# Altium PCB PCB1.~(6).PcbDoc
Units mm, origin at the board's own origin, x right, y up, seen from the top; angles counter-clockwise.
Board outline 48.89 x 49.4 mm, 2 copper layers (Top Layer, Bottom Layer); 29 components, 25 nets, 116 pads, 0 vias.
Unrouted connection lines stored in the file: 7.
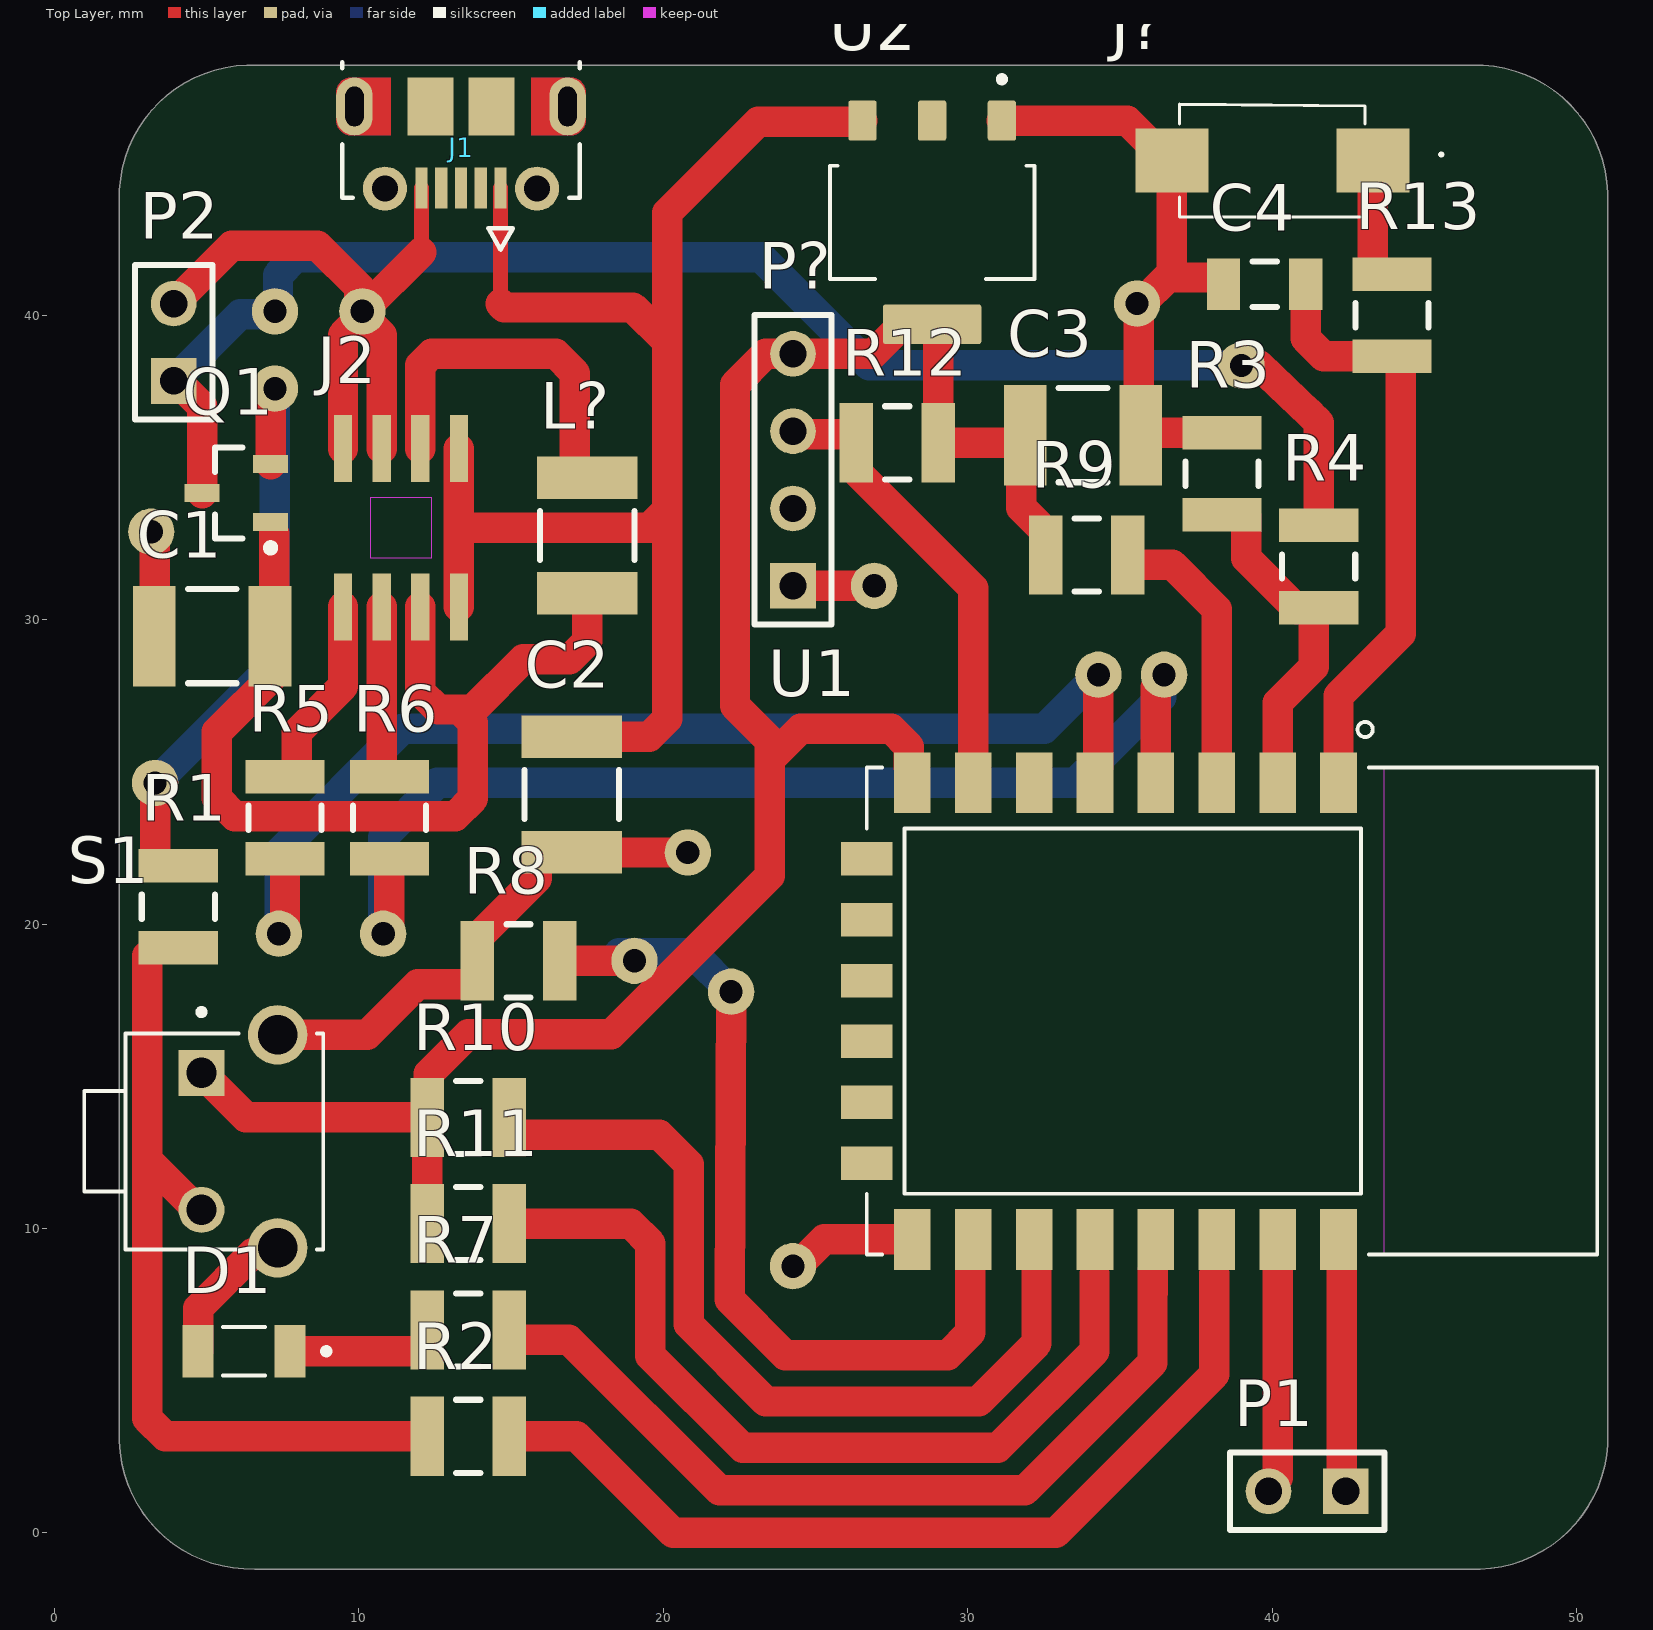
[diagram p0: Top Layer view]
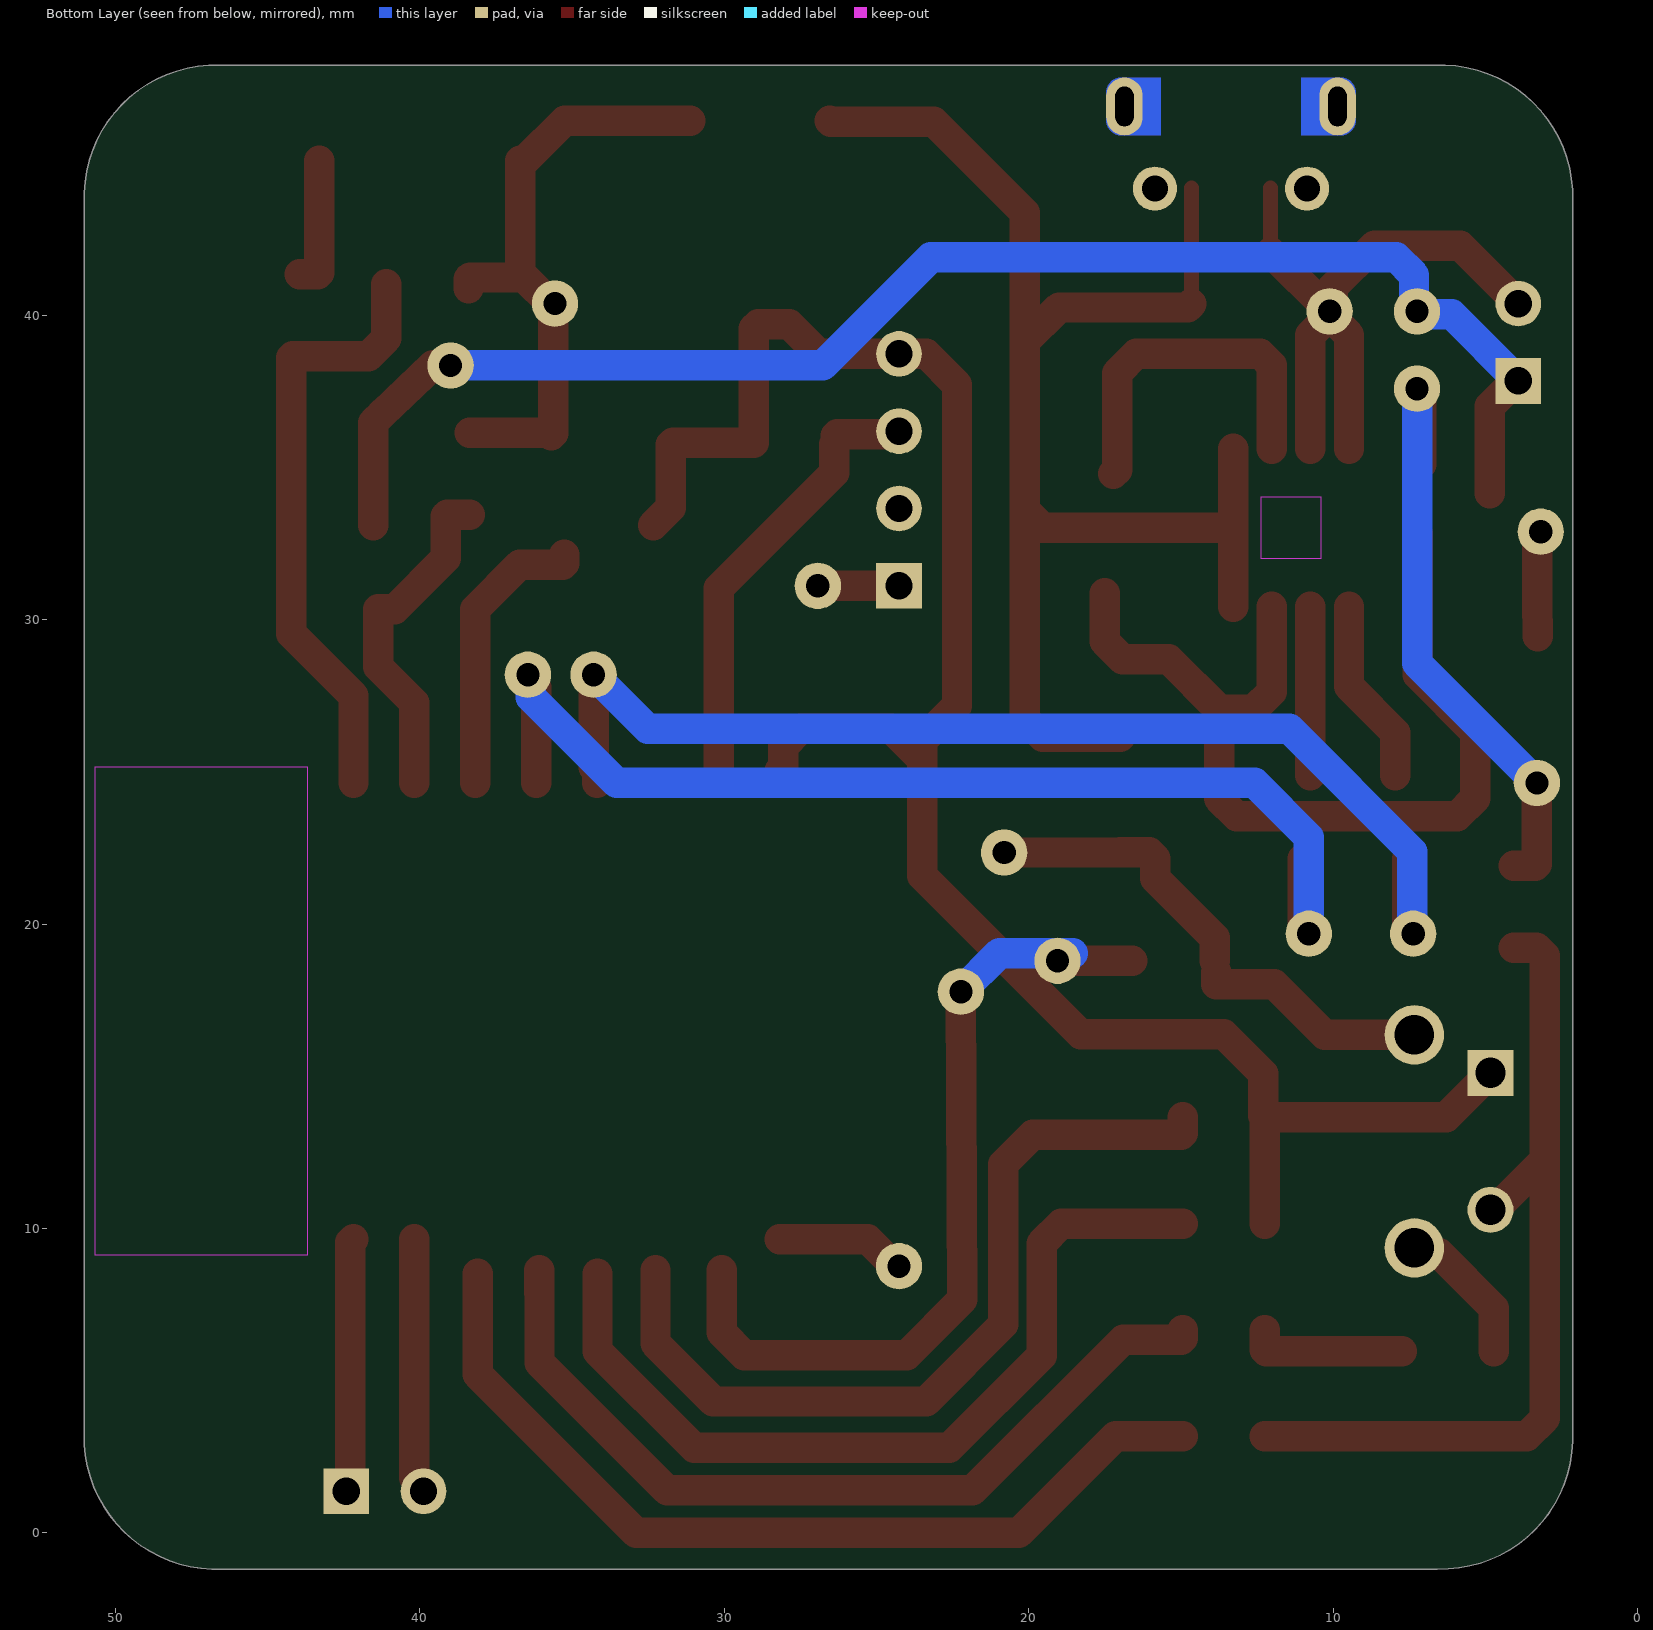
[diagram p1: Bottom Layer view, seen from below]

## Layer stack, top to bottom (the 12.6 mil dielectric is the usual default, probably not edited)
Top Solder: solder mask 0.0102, Solder Resist, Dk 3.5
Top Layer: signal copper 0.0356
Dielectric 1: dielectric 0.32, FR-4, Dk 4.8
Bottom Layer: signal copper 0.0356
Bottom Solder: solder mask 0.0102, Solder Resist, Dk 3.5

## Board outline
2.127,3.006 2.127,43.773 cw(c6.445,43.9) 6.318,48.218 46.577,48.218 cw(c46.704,43.9) 51.022,44.027 51.022,3.26 cw(c46.704,3.133) 46.831,-1.185 6.572,-1.185 cw(c6.445,3.133)

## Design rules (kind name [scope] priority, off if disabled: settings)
Clearance [All] p1: gap=0.254 ignorepadtopadclearanceinfootprint=FALSE except(0: Arc-Hole Track-Hole SMDPad-Hole THPad-Hole Via-Hole Fill-Hole Poly-Hole Region-Hole Text-Hole)
PolygonConnect [All] p1: connectstyle=Relief reliefconductorwidth=0.254 reliefentries=4 polygonreliefangle="90 Angle" airgapwidth=0.254
RoomDefinition Sheet1 [InComponentClass('Sheet1')] p1: confinementstyle=ConfineIn formatcopy=TRUE lockcomponents=FALSE outline 157.702,-50.588 350.234,-50.588 350.234,-19.854 157.702,-19.854
RoutingVias [All] p1: holewidth=0.711 width=1.27 viastyle="Through Hole" minholewidth=0.711 minwidth=1.27 maxholewidth=0.711 maxwidth=1.27
SolderMaskExpansion [All] p1: expansion=0.102 istentingtop=FALSE
Width [All] p1: maxlimit=1 minlimit=1 preferedwidth=1 minimp=50.000000 maximp=50.000000 favimp=50.000000
30 further rules are at their usual default settings.

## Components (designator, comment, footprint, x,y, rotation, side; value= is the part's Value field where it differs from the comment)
C1 "" 1812 5.177,29.464 r180 top value=10uF
C2 "" 1812 16.993,24.257 r270 top value=10uF
C3 "" 1812 33.782,36.068 r0 top value=10uF
C4 "" C1206 39.751,41.021 r0 top value=100pF
D1 "LED" LEDC3216X120N 6.223,5.969 r180 top
J1 "1050170001" MOLEX_1050170001 13.351,48.313 r180 top
J2 "L9110" SO-08 11.379,33.02 r0 top
J? "SWITCH" PTS636SM25FSMTRLFS 40.005,45.085 r180 top
L? "Inductor" INDC4532 17.501,32.766 r90 top value=47uH
P1 "Battery" HDR1X2 42.418,1.37 r180 top
P2 "Battery" HDR1X2 3.912,37.846 r90 top
P? "Header 4" HDR1X4 24.257,31.115 r90 top
Q1 "PNP" SOT-23B_N 5.969,34.163 r180 top
R1 "" 14-1210 4.064,20.574 r90 top value=1K
R2 "" 14-1210 13.589,3.175 r0 top value=1K
R3 "" 14-1210 38.354,34.798 r90 top value=1K
R4 "" 14-1210 41.529,31.75 r90 top value=1K
R5 "" 14-1210 7.569,23.495 r270 top value=1K
R6 "" 14-1210 10.998,23.495 r270 top value=1K
R7 "" 14-1210 13.589,6.668 r180 top value=1K
R8 "" 14-1210 15.24,18.796 r180 top value=1K
R9 "" 14-1210 33.909,32.131 r180 top value=1K
R10 "" 14-1210 13.589,13.652 r180 top value=1K
R11 "" 14-1210 13.589,10.16 r180 top value=1K
R12 "" 14-1210 27.686,35.814 r180 top value=1K
R13 "" 14-1210 43.942,40.005 r90 top value=1K
S1 "TL1105VF160Q" SW_TL1105VF160Q 4.826,12.863 r270 top
U1 "ESP8266-12E/ESP-12E" XCVR_ESP8266-12E/ESP-12E 35.179,17.145 r270 top
U2 "AMS1117" SOT229P700X180-4N 28.829,43.053 r270 top

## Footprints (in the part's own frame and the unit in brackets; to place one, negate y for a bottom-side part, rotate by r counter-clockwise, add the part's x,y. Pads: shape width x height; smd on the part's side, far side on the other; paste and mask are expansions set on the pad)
14-1210 [mm] "Chip Resistor, Body 3.2x2.5mm, IPC High Density"
  rect 1.1x2.6 smd: 1(-1.35,0) 2(1.35,0)
  silkscreen extent -0.4,-1.2 0.4,1.2, body extent -1.68,-1.32 1.68,1.32, height 0.9
1812 [mm] "Chip Capacitor, Body 4.5x3.2mm, IPC High Density"
  rect 1.4x3.3 smd: 1(-1.9,0) 2(1.9,0)
  silkscreen extent -0.8,-1.55 0.8,1.55, body extent -2.4,-1.7 2.4,1.7, height 1.4
C1206 [mm] "Chip Capacitor, Body 3.2x1.6mm, IPC High Density"
  rect 1.1x1.7 smd: 1(-1.35,0) 2(1.35,0)
  silkscreen extent -0.4,-0.75 0.4,0.75, body extent -1.7,-0.9 1.7,0.9, height 1.3
HDR1X2 [mm] "Connector; Header; 2 Position"
  rect 1.5x1.5 hole 0.9: 1(0,0)
  round 1.5 hole 0.9: 2(2.54,0)
  silkscreen extent -1.27,-1.27 3.81,1.27
HDR1X4 [mm] "Connector; Header; 4 Position"
  rect 1.5x1.5 hole 0.9: 1(0,0)
  round 1.5 hole 0.9: 2(2.54,0) 3(5.08,0) 4(7.62,0)
  silkscreen extent -1.27,-1.27 8.89,1.27
INDC4532 [mm] "Chip Inductor, Body 4.5x3.2mm, IPC High Density"
  rect 1.4x3.3 smd: 1(-1.9,0) 2(1.9,0)
  silkscreen extent -0.8,-1.55 0.8,1.55, body extent -2.4,-1.7 2.4,1.7, height 0.55
LEDC3216X120N [mm]
  rect 1.01x1.73 smd: NEG(1.51,0) POS(-1.51,0)
  silkscreen extent -2.8,-0.8 0.68,0.8, body extent -1.6,-0.8 1.6,0.8, height 1.2
MOLEX_1050170001 [mm]
  rect 0.4x1.35 smd mask+0.064: 1(-1.3,4.125) 2(-0.65,4.125) 3(0,4.125) 4(0.65,4.125) 5(1.3,4.125)
  round 1.45 hole 0.85 mask+0.064: SH1(-2.5,4.15) SH2(2.5,4.15)
  oval 1.2x1.9 hole 0.6 slot 1.3 at 90 deg mask+0: SH3(-3.5,1.45) SH6(3.5,1.45)
  rect 1.5x1.9 smd mask+0.064: SH4(-1,1.45) SH5(1,1.45)
  Top Layer region: -2.3,0.5 -3.6,0.5 -3.626,0.501 -3.652,0.503 -3.678,0.506 -3.704,0.511 -3.729,0.517 -3.755,0.524 -3.779,0.533 -3.803,0.543 -3.827,0.554 -3.85,0.567 -3.872,0.581 -3.894,0.595 -3.915,0.611 -3.935,0.628 -3.954,0.646 -3.972,0.665 -3.989,0.685 -4.005,0.706 -4.019,0.728 -4.033,0.75 -4.046,0.773 -4.057,0.797 -4.067,0.821 -4.076,0.845 -4.083,0.871 -4.089,0.896 -4.094,0.922 -4.097,0.948 -4.099,0.974 -4.1,1 -4.1,1.9 -4.099,1.926 -4.097,1.952 -4.094,1.978 -4.089,2.004 -4.083,2.029 -4.076,2.055 -4.067,2.079 -4.057,2.103 -4.046,2.127 -4.033,2.15 -4.019,2.172 -4.005,2.194 -3.989,2.215 -3.972,2.235 -3.954,2.254 -3.935,2.272 -3.915,2.289 -3.894,2.305 -3.872,2.319 -3.85,2.333 -3.827,2.346 -3.803,2.357 -3.779,2.367 -3.755,2.376 -3.729,2.383 -3.704,2.389 -3.678,2.394 -3.652,2.397 -3.626,2.399 -3.6,2.4 -2.3,2.4
  Top Layer region: 3.626,2.399 3.652,2.397 3.678,2.394 3.704,2.389 3.729,2.383 3.755,2.376 3.779,2.367 3.803,2.357 3.827,2.346 3.85,2.333 3.872,2.319 3.894,2.305 3.915,2.289 3.935,2.272 3.954,2.254 3.972,2.235 3.989,2.215 4.005,2.194 4.019,2.172 4.033,2.15 4.046,2.127 4.057,2.103 4.067,2.079 4.076,2.055 4.083,2.029 4.089,2.004 4.094,1.978 4.097,1.952 4.099,1.926 4.1,1.9 4.1,1 4.099,0.974 4.097,0.948 4.094,0.922 4.089,0.896 4.083,0.871 4.076,0.845 4.067,0.821 4.057,0.797 4.046,0.773 4.033,0.75 4.019,0.728 4.005,0.706 3.989,0.685 3.972,0.665 3.954,0.646 3.935,0.628 3.915,0.611 3.894,0.595 3.872,0.581 3.85,0.567 3.827,0.554 3.803,0.543 3.779,0.533 3.755,0.524 3.729,0.517 3.704,0.511 3.678,0.506 3.652,0.503 3.626,0.501 3.6,0.5 2.3,0.5 2.3,2.4 3.6,2.4
  Bottom Layer region: 3.626,2.399 3.652,2.397 3.678,2.394 3.704,2.389 3.729,2.383 3.755,2.376 3.779,2.367 3.803,2.357 3.827,2.346 3.85,2.333 3.872,2.319 3.894,2.305 3.915,2.289 3.935,2.272 3.954,2.254 3.972,2.235 3.989,2.215 4.005,2.194 4.019,2.172 4.033,2.15 4.046,2.127 4.057,2.103 4.067,2.079 4.076,2.055 4.083,2.029 4.089,2.004 4.094,1.978 4.097,1.952 4.099,1.926 4.1,1.9 4.1,1 4.099,0.974 4.097,0.948 4.094,0.922 4.089,0.896 4.083,0.871 4.076,0.845 4.067,0.821 4.057,0.797 4.046,0.773 4.033,0.75 4.019,0.728 4.005,0.706 3.989,0.685 3.972,0.665 3.954,0.646 3.935,0.628 3.915,0.611 3.894,0.595 3.872,0.581 3.85,0.567 3.827,0.554 3.803,0.543 3.779,0.533 3.755,0.524 3.729,0.517 3.704,0.511 3.678,0.506 3.652,0.503 3.626,0.501 3.6,0.5 2.3,0.5 2.3,2.4 3.6,2.4
  Bottom Layer region: -2.3,0.5 -3.6,0.5 -3.626,0.501 -3.652,0.503 -3.678,0.506 -3.704,0.511 -3.729,0.517 -3.755,0.524 -3.779,0.533 -3.803,0.543 -3.827,0.554 -3.85,0.567 -3.872,0.581 -3.894,0.595 -3.915,0.611 -3.935,0.628 -3.954,0.646 -3.972,0.665 -3.989,0.685 -4.005,0.706 -4.019,0.728 -4.033,0.75 -4.046,0.773 -4.057,0.797 -4.067,0.821 -4.076,0.845 -4.083,0.871 -4.089,0.896 -4.094,0.922 -4.097,0.948 -4.099,0.974 -4.1,1 -4.1,1.9 -4.099,1.926 -4.097,1.952 -4.094,1.978 -4.089,2.004 -4.083,2.029 -4.076,2.055 -4.067,2.079 -4.057,2.103 -4.046,2.127 -4.033,2.15 -4.019,2.172 -4.005,2.194 -3.989,2.215 -3.972,2.235 -3.954,2.254 -3.935,2.272 -3.915,2.289 -3.894,2.305 -3.872,2.319 -3.85,2.333 -3.827,2.346 -3.803,2.357 -3.779,2.367 -3.755,2.376 -3.729,2.383 -3.704,2.389 -3.678,2.394 -3.652,2.397 -3.626,2.399 -3.6,2.4 -2.3,2.4
  silkscreen extent -3.9,0 3.9,6.15
PTS636SM25FSMTRLFS [mm]
  rect 2.4x2.1 smd: 1(-3.3,0) 2(3.3,0)
  silkscreen extent -5.6,-1.85 3.05,1.85, body extent -4.29,-2.8 4.29,0, height 1.85
SO-08 [mm]
  rect 0.6x2.2 smd: 1(-1.905,-2.6) 2(-0.635,-2.6) 3(0.635,-2.6) 4(1.905,-2.6) 5(1.905,2.6) 6(0.635,2.6) 7(-0.635,2.6) 8(-1.905,2.6)
  Keep-Out Layer region: 1,-1 -1,-1 -1,1 1,1
SOT229P700X180-4N [mm]
  rrect15% 1.31x0.93 smd: 1(-3.345,2.29) 2(-3.345,0) 3(-3.345,-2.29)
  rrect15% 1.31x3.24 smd: 4(3.345,0)
  silkscreen extent -4.8,-3.36 1.86,3.36, body extent -3.25,-3.5 3.25,3.5, height 1.8
SOT-23B_N [mm] "SOT23, 3-Leads, Body 2.9x1.3mm, Pitch 0.95mm, Lead Span 2.4mm, IPC Medium Density"
  rect 1.15x0.6 smd: 1(-1.125,0.95) 2(-1.125,-0.95) 3(1.125,0)
  silkscreen extent -1.25,-1.5 0.7,1.92, body extent -0.7,-1.5 0.7,1.5, height 1.14
SW_TL1105VF160Q [mm]
  rect 1.508x1.508 / inner round 1.508 / far side rect 1.508x1.508 hole 1 mask+0.102: 1(-2.25,0)
  round 1.508 hole 1 mask+0.102: 2(2.25,0)
  round 1.95 hole 1.3 mask+0.102: S1(-3.5,2.5) S2(3.5,2.5)
  silkscreen extent -4.35,-3.85 3.55,4, body extent -7.7,-4.64 3.3,3.21, height 4.2
XCVR_ESP8266-12E/ESP-12E [mm]
  rect 2x1.2 smd: 1(-7.5,7) 2(-7.5,5) 3(-7.5,3) 4(-7.5,1) 5(-7.5,-1) 6(-7.5,-3) 7(-7.5,-5) 8(-7.5,-7) 15(7.5,-7) 16(7.5,-5) 17(7.5,-3) 18(7.5,-1) 19(7.5,1) 20(7.5,3) 21(7.5,5) 22(7.5,7)
  rect 1.1x1.7 smd: 9(-5,-8.5) 10(-3,-8.5) 11(-1,-8.5) 12(1,-8.5) 13(3,-8.5) 14(5,-8.5)
  Keep-Out Layer region: 8,8.51 -8.009,8.51 -8.009,15.5 8,15.5
  Keep-Out Layer region: 8,8.51 -8.009,8.51 -8.009,15.5 8,15.5
  silkscreen extent -9.5,-8.5 8,15.5, body extent -8,-12 8,12, height 3

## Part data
C1 C2 C3: library part "Cap Pol3", "Polarized Capacitor (Surface Mount)"
C4: library part "Cap Semi", "Capacitor (Semiconductor SIM Model)"
D1: library part LHN974_RED_LED_1206, "2.6 V Red LED SMD", Package=None
J1: "USB - micro B USB 2.0 Receptacle Connector 5 Position Surface Mount, Right Angle; Through Hole", Package=None
J2: "Motor control driver chip", Package=Package
J?: library part PTS636_SM25F_SMTR_LFS, "Tactile Switch SPST-NO Top Actuated Surface Mount", Package=None
P1 P2: library part "Header 2", "Header, 2-Pin"
P?: "Header, 4-Pin"
Q1: "PNP Bipolar Transistor"
R1 R2 R3 R4 R5 R6 R7 R8 R9 R10 R11 R12 R13: library part Res3, "Resistor"
S1: "Tactile Switch, TL1105 Series, SPST-NO, 3.85mm Side Actuated, 0.05A, 12VDC, PC", Package=None
U1: "This WiFi module has a 32-bit MCU micro and clock speeds supporting 80 MHz or 160 MHz. Supports the RTOS and integrated Wi-Fi MAC/BB/RF/PA/LNA, and has an on-board antenna.", Package=None
U2: "1A LOW DROPOUT VOLTAGE REGULATOR SOT-223", Package="SOT-223 Seeed Technology"

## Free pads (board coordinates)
  round 1.524 hole 0.762: 2(10.109,40.132) 3(20.803,22.352) 4(3.175,32.893) 5(3.302,24.638) 6(7.239,37.592) 7(22.225,17.78) 8(19.05,18.796) 9(35.56,40.386) 10(26.924,31.115) 11(24.257,8.763) 12(7.366,19.685) 13(10.795,19.685) 14(34.29,28.194) 15(36.449,28.194) 16(7.239,40.132) 17(38.989,38.354)

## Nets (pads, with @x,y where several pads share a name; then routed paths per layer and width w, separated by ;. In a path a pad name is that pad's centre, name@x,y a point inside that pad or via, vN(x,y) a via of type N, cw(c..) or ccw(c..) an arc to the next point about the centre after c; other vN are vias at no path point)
+3.3: C3.1 P?.4 R9.2 R10.2 R11.2 R12.1 S1.1 U1.8 U2.2 U2.4 | length 66.9
  Top Layer w1: S1.1 6.287,13.652 R10.2 ; R11.2 R10.2 ; U1.8 28.179,25.045 28.067,25.157 28.067,25.83 27.481,26.416 24.511,26.416 23.495,25.4 ; R9.2@32.338,33.1 31.752,33.686 31.752,35.744 31.682,35.814 R12.1 29.036,39.553 28.881,39.708 U2.4 27.864,39.708 26.891,38.735 P?.4 23.368,38.735 22.352,37.719 22.352,27.178 23.495,26.035 23.495,25.4 ; R10.2 12.289,13.702 12.289,15.083 13.589,16.383 18.288,16.383 23.495,21.59 23.495,25.4
+5: C2.1 J1.1 J2.4 J2.5 U2.3 | length 49.8
  Top Layer w0.5: 14.651,40.386 J1.1
  Top Layer w1: J2.4 13.284,33.02 ; J2.5 13.284,33.02 ; 14.651,40.386 14.778,40.259 18.999,40.259 20.125,39.133 ; C2.1 19.539,26.157 20.125,26.743 20.125,33.606 ; U2.3 26.539,46.39 26.504,46.355 23.114,46.355 20.125,43.366 20.125,39.133 ; 13.284,33.02 19.539,33.02 20.125,33.606 ; 20.125,33.606 20.125,39.133
ADC: R3.1 R4.1 U1.2 | length 11.3
  Top Layer w1: R3.1 39.104,33.448 39.154,33.398 39.154,32.025 40.829,30.35 41.364,30.35 41.364,28.457 40.179,27.272 U1.2
Battery: P2.1 pad.16 pad.17 Q1.3 R4.2 | length 49.7
  Top Layer w1: P2.1 4.162,37.596 4.258,37.596 4.844,37.01 Q1.3 ; pad.17 39.141,38.358 39.154,38.358 39.566,38.358 41.227,36.78 41.236,36.771 41.529,36.478 R4.2
  Bottom Layer w1: P2.1 6.097,40.032 7.139,40.032 7.339,40.232 7.339,41.324 7.925,41.91 23.209,41.91 26.765,38.354 pad.17
EN: R9.1 U1.3 | length 9.5
  Top Layer w1: R9.1 35.259,31.856 35.309,31.806 36.723,31.806 38.179,30.35 U1.3
GND: C1.2 C2.2 C3.2 C4.1 D1.NEG J1.5 J2.7 J2.8 J?.2 P2.2 P?.1 pad.2 pad.3 pad.4 pad.9 pad.10 pad.11 R3.2 R8.2 S1.S1 S1.S2 U1.15 U2.1 | length 75.3
  Top Layer w0.5: 12.051,42.074 J1.5
  Top Layer w1: pad.4 3.215,32.918 3.289,32.843 3.289,30.614 C1.2 ; P2.2 5.817,42.291 8.636,42.291 10.009,40.918 10.009,40.232 pad.2 ; D1.NEG 4.718,5.974 4.718,7.385 6.514,9.181 7.144,9.181 S1.S2 ; S1.S1 10.267,16.363 11.928,18.024 13.84,18.024 R8.2@13.84,18.415 ; J2.8 9.474,39.355 pad.2@10.109,39.99 ; J2.7 10.744,39.355 pad.2@10.109,39.99 ; 12.051,42.074 pad.2 ; R8.2 13.89,19.546 15.843,21.499 15.843,22.157 16.043,22.357 C2.2 16.995,22.354 20.8,22.354 pad.3 ; pad.11 24.399,8.763 25.281,9.645 U1.15 ; P?.1 pad.10 ; U2.1 35.242,46.398 36.555,45.085 J?.2 36.705,41.48 36.941,41.244 ; R3.2 35.762,36.148 C3.2 35.621,36.129 35.621,40.325 pad.9 35.702,40.386 36.56,41.244 36.941,41.244 ; C4.1@38.401,40.894 C4.1 38.401,41.194 38.351,41.244 36.941,41.244 ; pad.2@10.109,39.99 pad.2
GPIO0: R11.1 U1.18 | length 28.3
  Top Layer w1: R11.1 18.923,10.16 19.574,9.509 19.574,5.826 22.606,2.794 30.988,2.794 34.163,5.969 34.163,8.519
GPIO2: R10.1 U1.17 | length 27.8
  Top Layer w1: R10.1 14.939,13.131 14.989,13.081 19.861,13.081 20.828,12.114 20.828,6.858 23.368,4.318 30.353,4.318 32.258,6.223 32.258,8.636
GPIO4: R7.1 U1.19 | length 28.3
  Top Layer w1: R7.1 14.939,6.4 14.989,6.35 16.891,6.35 21.844,1.397 31.877,1.397 36.068,5.588 36.068,7.879 36.079,7.89 36.079,8.636
GPIO5: R2.2 U1.20 | length 29.9
  Top Layer w1: R2.2 17.145,3.175 20.32,0 32.893,0 38.1,5.207 38.1,8.509
GPIO13: P?.3 R12.2 U1.7 | length 15.1
  Top Layer w1: P?.3@24.257,36.099 26.286,36.099 26.336,36.049 R12.2 26.386,35.764 26.386,34.828 30.179,31.035 U1.7
GPIO14: pad.12 pad.14 R5.2 U1.5 | length 38.1
  Top Layer w1: pad.12 7.366,19.827 7.569,20.03 R5.2 ; U1.5 34.179,25.045 34.29,25.156 pad.14
  Bottom Layer w1: pad.12 7.394,19.713 7.394,22.38 11.43,26.416 32.512,26.416 pad.14
GPIO15: pad.7 pad.8 R8.1 U1.16 | length 27.8
  Top Layer w1: R8.1 pad.8 ; pad.7 22.177,7.668 24.003,5.842 29.337,5.842 30.079,6.584 30.079,8.636
  Bottom Layer w1: pad.8@18.542,19.05 20.955,19.05 pad.7
GPIO16: pad.13 pad.15 R6.2 U1.4 | length 37.6
  Top Layer w1: pad.13 10.795,19.827 10.998,20.03 R6.2 ; U1.4 36.179,27.782 36.449,28.052 pad.15
  Bottom Layer w1: pad.13 10.795,22.86 12.573,24.638 33.528,24.638 36.349,27.459 36.349,28.094 pad.15
L1: J2.1 R5.1 | length 6.2
  Top Layer w1: R5.1@7.95,24.895 7.95,26.289 9.474,27.813 J2.1
L2: J2.2 R6.1 | length 5.5
  Top Layer w1: R6.1@10.744,24.895 J2.2
NetC1_1: C1.1 J2.3 L?.1 Q1.1 | length 32.5
  Top Layer w1: 7.214,32.832 7.214,28.194 5.334,26.314 5.334,24.127 5.92,23.541 13.157,23.541 13.743,24.127 13.743,26.617 13.31,27.051 ; J2.3 12.014,27.637 12.6,27.051 13.31,27.051 ; L?.1 17.501,29.288 16.915,28.702 15.394,28.702 13.743,27.051 13.31,27.051
NetD1_POS: D1.POS R7.2 | length 5.2
  Top Layer w1: D1.POS 12.189,5.969 12.239,6.019 R7.2
NetJ2_6: J2.6 L?.2 | length 11.6
  Top Layer w1: J2.6 12.014,38.354 12.395,38.735 16.459,38.735 17.094,38.1 17.094,34.92 L?.2@17.221,34.793
NetJ?_1: J?.1 R13.2 | length 4.3
  Top Layer w1: J?.1 43.305,41.405 43.355,41.355 R13.2
NetR1_1: R1.1 R2.1 S1.2 | length 28.2
  Top Layer w1: R1.1 3.314,19.224 3.048,18.958 3.048,12.254 ; S1.2 4.689,10.613 3.048,12.254 ; R2.1 3.634,3.175 3.048,3.761 3.048,12.254
ON/OFF: pad.5 pad.6 Q1.2 R1.2 | length 20.6
  Top Layer w1: pad.5 3.302,21.974 3.352,21.924 R1.2 ; Q1.2 7.094,37.447 pad.6
  Bottom Layer w1: pad.5 7.239,28.575 pad.6
RESET: C4.2 R13.1 U1.1 | length 20
  Top Layer w1: C4.2 41.101,39.241 41.687,38.655 44.168,38.655 44.218,38.605 44.218,29.538 42.179,27.499 U1.1
RX: P1.2 U1.21 | length 8.4
  Top Layer w1: P1.2 39.878,1.505 40.179,1.806 U1.21
TX: P1.1 U1.22 | length 8.4
  Top Layer w1: U1.22 42.279,9.545 42.279,1.509 P1.1
pads on no net: J1.2 J1.3 J1.4 J1.SH1 J1.SH2 J1.SH3 J1.SH4 J1.SH5 J1.SH6 P?.2 U1.6 U1.9 U1.10 U1.11 U1.12 U1.13 U1.14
